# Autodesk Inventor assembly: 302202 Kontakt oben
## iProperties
Created: 2006-12
Part Number: 302202 Kontakt oben
Cost Center: 0 kg
Document SubType Name: Assembly
Designer: Martin
Authority: 0 mm^3
Mass: 15216.6 g
Surface Area: 3584.81 cm^2
Volume: 2091.81 cm^3
Density: 7.27435 g/cm^3
SaveDate: 2004-08-02
SaveTime: 16:43
TotalMass: 0 kg
TotalVolume: 0 mm^3
Author: Martin
